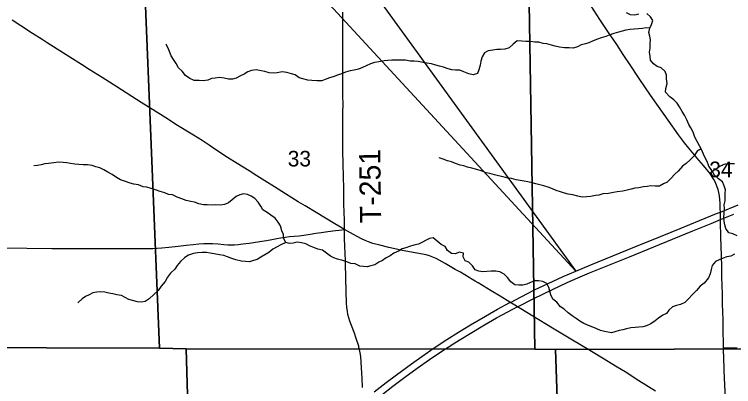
# Model space of a CAD drawing. Extents: x 0 to 34, y 0 to 22.
# Drawn here: x 13.115 to 15.039, y 13.199 to 14.196 of the extents above; entities that cross this region are included whole.
import ezdxf

# ---------------------------------------------------------------- set-up
doc = ezdxf.new("R2010")
doc.units = 0
for name, color, linetype in [('GM_X_County_Road', 7, 'Continuous'), ('GM_X_Interstate_Route', 7, 'Continuous'), ('GM_X_Minor_River', 7, 'Continuous'), ('GM_X_Section', 7, 'Continuous'), ('GM_X_Section_Text', 7, 'Continuous'), ('GM_X_State_Route', 7, 'Continuous'), ('GM_X_Township_Road', 7, 'Continuous'), ('GM_X_Township_Road_Text', 7, 'Continuous'), ('SH_Text', 7, 'Continuous')]:
    doc.layers.add(name, color=color, linetype=linetype)

msp = doc.modelspace()

# ---------------------------------------------------------------- linework, layer by layer
at = {"layer": 'GM_X_County_Road'}
for points in [[(14.9755, 13.7707), (14.9668, 13.7812), (14.9586, 13.7912), (14.9458, 13.8057), (14.9192, 13.8373), (14.9077, 13.8519), (14.8919, 13.8735), (14.8636, 13.9126), (14.8227, 13.9707), (14.8053, 13.9962), (14.7826, 14.03), (14.7641, 14.0579), (14.7439, 14.0885), (14.7265, 14.1152), (14.7027, 14.1505), (14.6816, 14.1823), (14.6568, 14.2195)], [(15.0124, 13.3029), (15.0119, 13.3151), (15.0111, 13.3488), (15.0107, 13.3777), (15.0096, 13.4211), (15.0092, 13.4459), (15.0085, 13.4706), (15.0079, 13.492), (15.0071, 13.5168), (15.0063, 13.5534), (15.0059, 13.5722), (15.0051, 13.6031), (15.0043, 13.637), (15.0041, 13.6463), (15.0036, 13.6567), (15.0036, 13.6668), (15.0033, 13.6758), (15.0027, 13.6908), (15.0022, 13.6999), (15.0012, 13.7102), (14.9998, 13.7188), (14.9979, 13.7268), (14.9946, 13.7362), (14.9908, 13.7455), (14.9865, 13.7537), (14.9819, 13.7612), (14.9789, 13.7658), (14.9755, 13.7707)], [(14.0369, 13.3041), (14.0367, 13.305), (14.0361, 13.3074), (14.0298, 13.3278), (14.0247, 13.3424), (14.0169, 13.3627), (14.0126, 13.3744), (14.0099, 13.3833), (14.0075, 13.3924), (14.0058, 13.4016), (14.0045, 13.4109), (14.0037, 13.4233), (14.0035, 13.4294), (14.003, 13.4475), (14.0025, 13.4631), (14.002, 13.4819), (14.0015, 13.5016), (14.001, 13.5178), (14.0005, 13.5359), (13.9996, 13.5557), (13.9989, 13.5752), (13.9983, 13.5957), (13.9978, 13.6199)], [(14.0465, 13.1967), (14.0456, 13.2216), (14.044, 13.2495), (14.0431, 13.2649), (14.0416, 13.2803), (14.0402, 13.2895), (14.0384, 13.2985), (14.0369, 13.3041)], [(15.0175, 13.1667), (15.0173, 13.1721), (15.0166, 13.1852), (15.016, 13.2036), (15.015, 13.2225), (15.0142, 13.2429), (15.0126, 13.2796), (15.0123, 13.2934), (15.0124, 13.3029)], [(15.0124, 13.3029), (15.0489, 13.3027)]]:
    msp.add_lwpolyline(points, dxfattribs=at)
at = {"layer": 'GM_X_Interstate_Route'}
for points in [[(14.0779, 13.1856), (14.1097, 13.2105), (14.1369, 13.2311), (14.1771, 13.2604), (14.2049, 13.2801), (14.2382, 13.303), (14.2411, 13.3049), (14.2719, 13.3252), (14.3033, 13.3452), (14.3351, 13.3645), (14.3753, 13.3881), (14.4077, 13.4064), (14.4405, 13.4241), (14.4418, 13.4247), (14.4708, 13.4399), (14.5068, 13.458), (14.5432, 13.4755), (14.5827, 13.4937), (14.6168, 13.5087), (14.6568, 13.5256), (14.7749, 13.5734), (14.8439, 13.6016), (14.8957, 13.6227), (14.9475, 13.6438), (14.9935, 13.6627), (15.0036, 13.6668), (15.051, 13.6862)], [(14.4597, 13.4127), (14.4608, 13.4132), (14.5043, 13.4348), (14.5546, 13.4593), (14.594, 13.4779), (14.6224, 13.4905), (14.6539, 13.5039), (14.7605, 13.5469), (14.8755, 13.594), (14.9302, 13.6164), (14.9792, 13.6362), (15.0041, 13.6463), (15.0396, 13.6607)], [(14.0978, 13.1775), (14.1273, 13.2004), (14.1596, 13.2247), (14.1923, 13.2483), (14.2255, 13.2715), (14.2616, 13.2958), (14.2757, 13.3049), (14.2929, 13.3161), (14.33, 13.339), (14.3726, 13.3646), (14.4049, 13.3832), (14.4349, 13.3998), (14.4597, 13.4127)]]:
    msp.add_lwpolyline(points, dxfattribs=at)
at = {"layer": 'GM_X_Minor_River'}
for points in [[(14.7852, 14.1967), (14.775, 14.1938), (14.7636, 14.1951), (14.7527, 14.2001)], [(15.0483, 13.6026), (15.0374, 13.6084), (15.0264, 13.6108), (15.0185, 13.6223), (15.0152, 13.6322), (15.0142, 13.6424), (15.0127, 13.6523), (15.0136, 13.6633), (15.0145, 13.6754), (15.0138, 13.6861), (15.0162, 13.697), (15.0163, 13.7168), (15.0172, 13.7266), (15.0138, 13.7369), (15.0094, 13.7479), (14.9985, 13.7556), (14.988, 13.7656), (14.9805, 13.7778), (14.973, 13.7893), (14.9682, 13.8019), (14.9634, 13.8118), (14.9589, 13.8221), (14.9533, 13.8339), (14.9477, 13.8438), (14.9414, 13.8556), (14.9354, 13.8674), (14.9306, 13.8808), (14.9247, 13.8918), (14.9194, 13.9014), (14.9135, 13.9132), (14.9075, 13.9258), (14.9016, 13.9357), (14.8945, 13.9483), (14.8877, 13.9578), (14.8787, 13.9674), (14.8682, 13.9755), (14.8569, 13.9873), (14.8578, 13.9976), (14.8613, 14.0108), (14.8599, 14.023), (14.8592, 14.0336), (14.8559, 14.0431), (14.8454, 14.0527), (14.8348, 14.0562), (14.8246, 14.0632), (14.8168, 14.0735), (14.8157, 14.0834), (14.8143, 14.0951), (14.8155, 14.1054), (14.8156, 14.1179), (14.8165, 14.1274), (14.815, 14.1376), (14.8121, 14.1475), (14.8152, 14.1593), (14.8195, 14.1691), (14.823, 14.1797), (14.8166, 14.1892), (14.8065, 14.198)], [(14.8152, 14.1593), (14.805, 14.1597), (14.7955, 14.1579), (14.7849, 14.1569), (14.7728, 14.1566), (14.7626, 14.1552), (14.7508, 14.1538), (14.7413, 14.1513), (14.7307, 14.1487), (14.7185, 14.145), (14.7064, 14.1402), (14.6969, 14.1369), (14.6847, 14.1328), (14.6749, 14.1295), (14.6635, 14.1247), (14.6521, 14.1202), (14.6426, 14.1173), (14.6316, 14.114), (14.6213, 14.1088), (14.6103, 14.1059), (14.5989, 14.1063), (14.5864, 14.1068), (14.5736, 14.1081), (14.5619, 14.1105), (14.5517, 14.1136), (14.5392, 14.1172), (14.5294, 14.1184), (14.518, 14.1212), (14.5074, 14.122), (14.4961, 14.1229), (14.4832, 14.1234), (14.4726, 14.1243), (14.4605, 14.1248), (14.4491, 14.1162), (14.4388, 14.1064), (14.4274, 14.1027), (14.4156, 14.1017), (14.4058, 14.1022), (14.3948, 14.1), (14.3826, 14.0982), (14.3724, 14.0926), (14.3666, 14.082), (14.3631, 14.0703), (14.3607, 14.0601), (14.3576, 14.0476), (14.3537, 14.0378), (14.342, 14.0337), (14.3306, 14.0369), (14.3174, 14.0423), (14.3069, 14.0462), (14.2947, 14.0463), (14.2849, 14.0476), (14.2751, 14.0503), (14.2634, 14.0546), (14.2524, 14.0577), (14.2422, 14.0601), (14.2305, 14.0633), (14.2188, 14.0657), (14.209, 14.0673), (14.195, 14.0697), (14.1847, 14.0709), (14.1738, 14.071), (14.1613, 14.073), (14.1382, 14.0733), (14.1249, 14.073), (14.114, 14.0724), (14.1041, 14.0713), (14.0901, 14.0692), (14.0783, 14.067), (14.0677, 14.0637), (14.0559, 14.0585), (14.0464, 14.0533), (14.0354, 14.0492), (14.024, 14.0467), (14.0134, 14.0445), (14.0008, 14.0408), (13.9898, 14.0371), (13.9792, 14.0335), (13.9678, 14.0286), (13.9579, 14.0261), (13.9469, 14.0212), (13.9374, 14.0183), (13.9238, 14.0177), (13.9109, 14.0193), (13.8999, 14.0202), (13.8871, 14.0233), (13.8765, 14.0265), (13.866, 14.0338), (13.8562, 14.0369), (13.8437, 14.0405), (13.8312, 14.0421), (13.8183, 14.0392), (13.8077, 14.0389), (13.7967, 14.0394), (13.785, 14.0429), (13.7752, 14.0445), (13.762, 14.0473), (13.7498, 14.0456), (13.7392, 14.0419), (13.7297, 14.0359), (13.7198, 14.031)], [(13.7198, 14.031), (13.7084, 14.0251), (13.6985, 14.0225), (13.6883, 14.0226), (13.6766, 14.0254), (13.6637, 14.027), (13.6523, 14.0253), (13.6428, 14.0242), (13.6322, 14.0201), (13.6201, 14.018), (13.6095, 14.0185), (13.5958, 14.019), (13.5842, 14.0244), (13.5729, 14.0321), (13.5642, 14.0439), (13.5545, 14.0528), (13.5481, 14.0642), (13.541, 14.0753), (13.5343, 14.0852), (13.5302, 14.0963), (13.5261, 14.1058), (13.5213, 14.1157), (13.5217, 14.1161)], [(14.9523, 13.8357), (14.9419, 13.8294), (14.9331, 13.817), (14.9224, 13.8069), (14.9121, 13.7971), (14.9026, 13.7892), (14.8911, 13.7764), (14.8816, 13.7682), (14.8713, 13.7565), (14.8609, 13.7464), (14.8514, 13.7419), (14.8404, 13.7359), (14.8294, 13.7364), (14.8177, 13.7365), (14.8082, 13.7355), (14.798, 13.7341), (14.7851, 13.7319), (14.7749, 13.7309), (14.7646, 13.7276), (14.754, 13.7254), (14.743, 13.7228), (14.7274, 13.7211), (14.7176, 13.7189), (14.7043, 13.716), (14.6891, 13.7154), (14.6789, 13.7121), (14.6694, 13.7107), (14.6565, 13.7081), (14.6467, 13.7071), (14.6342, 13.7068), (14.6224, 13.7088), (14.6088, 13.7124), (14.5967, 13.7148), (14.5865, 13.7172), (14.5764, 13.721), (14.5646, 13.7246), (14.5548, 13.7288), (14.5431, 13.7335), (14.5318, 13.737), (14.5208, 13.7398), (14.5103, 13.7426), (14.5001, 13.7449), (14.4887, 13.7477), (14.4789, 13.7493), (14.4573, 13.7533), (14.4453, 13.7565), (14.435, 13.7573), (14.423, 13.7612), (14.4097, 13.764), (14.3995, 13.7664), (14.3871, 13.7696), (14.3768, 13.7719), (14.364, 13.7766), (14.3523, 13.7805), (14.3387, 13.7841), (14.327, 13.7868), (14.3172, 13.7904), (14.3073, 13.7923), (14.2953, 13.7963), (14.2843, 13.8009), (14.2737, 13.8041), (14.2617, 13.8087), (14.2518, 13.8115), (14.2511, 13.8119)], [(14.1098, 13.5438), (14.0999, 13.5367), (14.0904, 13.5323), (14.079, 13.5255), (14.0684, 13.523), (14.0589, 13.52), (14.0487, 13.5205), (14.0388, 13.5221), (14.0264, 13.5276), (14.0151, 13.5292), (14.0041, 13.5331), (13.9939, 13.5374), (13.9799, 13.5409), (13.9701, 13.5441), (13.9603, 13.5487), (13.9498, 13.5564), (13.9392, 13.5649), (13.9271, 13.5676), (13.9162, 13.5715), (13.906, 13.575), (13.8951, 13.5812), (13.8834, 13.5844), (13.8716, 13.5864), (13.861, 13.5834), (13.8512, 13.5824), (13.841, 13.5848), (13.8354, 13.5966), (13.8351, 13.6068), (13.8306, 13.6168), (13.8273, 13.6297), (13.821, 13.64), (13.8123, 13.6499), (13.8007, 13.658), (13.7909, 13.6653), (13.78, 13.6723), (13.774, 13.6822), (13.7669, 13.6933), (13.7579, 13.7028), (13.7481, 13.7094), (13.7383, 13.714), (13.7281, 13.7157), (13.7182, 13.7131), (13.708, 13.7083), (13.6976, 13.6993), (13.6877, 13.6918), (13.6771, 13.6873), (13.6653, 13.6848), (13.6544, 13.6856), (13.6438, 13.6854), (13.6309, 13.6859), (13.621, 13.6863), (13.6089, 13.6887), (13.5972, 13.6934), (13.5867, 13.6946), (13.5746, 13.6978), (13.5629, 13.7025), (13.5508, 13.7068), (13.5383, 13.713), (13.5277, 13.7138), (13.5179, 13.7185), (13.5055, 13.722), (13.4923, 13.7263), (13.4813, 13.7294), (13.4696, 13.7334), (13.4598, 13.7342), (13.4473, 13.7393), (13.4344, 13.7417), (13.4246, 13.744), (13.4122, 13.7487), (13.3986, 13.7526), (13.3884, 13.7596), (13.3767, 13.7673), (13.365, 13.7735), (13.3545, 13.7796), (13.3439, 13.7847), (13.333, 13.7882), (13.3228, 13.7909), (13.3107, 13.793), (13.2989, 13.7927), (13.2876, 13.7939), (13.277, 13.7952), (13.2653, 13.7968), (13.2554, 13.7988), (13.2456, 13.7997), (13.2323, 13.8002), (13.221, 13.7988), (13.2066, 13.7963), (13.1963, 13.7956), (13.1869, 13.7934), (13.177, 13.7912), (13.1668, 13.7902), (13.1671, 13.7902)], [(13.841, 13.5848), (13.828, 13.5785), (13.8178, 13.5732), (13.8067, 13.5669), (13.796, 13.5583), (13.785, 13.5519), (13.7744, 13.5456), (13.7648, 13.54), (13.755, 13.5367), (13.7443, 13.533), (13.733, 13.5342), (13.7224, 13.5351), (13.7077, 13.539), (13.6967, 13.5426), (13.6854, 13.5465), (13.6756, 13.55), (13.6638, 13.552), (13.6498, 13.5548), (13.6389, 13.5564), (13.629, 13.5584), (13.6177, 13.5585), (13.6052, 13.5575), (13.5942, 13.5557), (13.5813, 13.5516), (13.5714, 13.5453), (13.5595, 13.534), (13.5507, 13.5239), (13.5442, 13.5141), (13.5332, 13.5028), (13.5251, 13.4919), (13.5182, 13.4805), (13.5082, 13.4681), (13.5002, 13.4568), (13.4758, 13.4343), (13.4651, 13.4276), (13.4556, 13.4254), (13.4446, 13.4266), (13.4344, 13.4294), (13.4216, 13.4329), (13.4118, 13.4376), (13.4016, 13.4434), (13.3895, 13.4446), (13.3789, 13.4481), (13.3676, 13.4498), (13.357, 13.4518), (13.3464, 13.453), (13.3354, 13.4524), (13.3252, 13.4506), (13.3153, 13.4453), (13.3058, 13.4405), (13.2963, 13.4341), (13.286, 13.4248), (13.2848, 13.424)], [(15.0414, 13.5541), (15.0312, 13.5489), (15.0213, 13.5471), (15.0107, 13.543), (15.0008, 13.5386), (14.9909, 13.5345), (14.9817, 13.5236), (14.979, 13.513), (14.9766, 13.5009), (14.9716, 13.4903), (14.9605, 13.4767), (14.9495, 13.4685), (14.9399, 13.4568), (14.9284, 13.4448), (14.9185, 13.4339), (14.9082, 13.4245), (14.8972, 13.4189), (14.8862, 13.4164), (14.8755, 13.4127), (14.866, 13.4044), (14.8595, 13.3946), (14.8496, 13.3902), (14.8385, 13.3827), (14.829, 13.3756), (14.818, 13.3673), (14.8062, 13.3621), (14.7963, 13.3596), (14.7853, 13.3585), (14.7755, 13.3575), (14.7641, 13.3568), (14.7523, 13.3543), (14.7429, 13.3517), (14.733, 13.3492), (14.7216, 13.3459), (14.7121, 13.3437), (14.6936, 13.3465), (14.6826, 13.3493), (14.6728, 13.3536), (14.6623, 13.3582), (14.6509, 13.3625), (14.6385, 13.3683), (14.6279, 13.3741), (14.6182, 13.3814), (14.6072, 13.3891), (14.5967, 13.3964), (14.5862, 13.4068), (14.5764, 13.4133), (14.5659, 13.4256), (14.5554, 13.4333), (14.5505, 13.4454), (14.5476, 13.455), (14.5446, 13.4648), (14.5394, 13.4751), (14.5285, 13.4809), (14.5168, 13.4822), (14.5062, 13.4823), (14.4955, 13.4778), (14.4856, 13.4734), (14.4754, 13.4708), (14.4644, 13.4713), (14.4542, 13.4718), (14.4433, 13.4795), (14.4339, 13.491), (14.4249, 13.5005), (14.414, 13.5063), (14.4034, 13.5083), (14.3905, 13.5088), (14.3788, 13.5078), (14.3678, 13.5068), (14.3579, 13.508), (14.3481, 13.5123), (14.3403, 13.5226), (14.3309, 13.5322), (14.3207, 13.5365), (14.3159, 13.5468), (14.3163, 13.5562), (14.3046, 13.559), (14.2947, 13.5546), (14.2841, 13.5554), (14.2736, 13.5635), (14.2673, 13.5742), (14.2567, 13.58), (14.2465, 13.5888), (14.2353, 13.598), (14.2258, 13.5962), (14.1965, 13.5806), (14.184, 13.5776), (14.1722, 13.5747), (14.1623, 13.571), (14.1525, 13.5681), (14.1426, 13.5621), (14.13, 13.5569), (14.1205, 13.5494), (14.1098, 13.5438)]]:
    msp.add_lwpolyline(points, dxfattribs=at)
at = {"layer": 'GM_X_Section'}
for points in [[(13.4623, 14.3061), (13.5034, 13.3022), (12.5967, 13.3052), (12.4929, 13.3075), (12.486, 14.3129), (12.9117, 14.2993)], [(14.4911, 14.2816), (14.5077, 13.2997), (13.5746, 13.3006), (13.5034, 13.3022), (13.4623, 14.3061), (13.6079, 14.3123), (13.9911, 14.2848)], [(15.5087, 14.2889), (15.5148, 13.3016), (14.5623, 13.2983), (14.5077, 13.2997), (14.4911, 14.2816)], [(13.5034, 13.3022), (13.5746, 13.3006), (13.6043, 12.2869), (12.6535, 12.2476), (12.5967, 13.3052)], [(14.5623, 13.2983), (14.5977, 12.2808), (13.6043, 12.2869), (13.5746, 13.3006), (14.5077, 13.2997)], [(15.5625, 13.3022), (15.5907, 12.2877), (15.0525, 12.2941), (14.5977, 12.2808), (14.5623, 13.2983), (15.5148, 13.3016)]]:
    msp.add_lwpolyline(points, close=True, dxfattribs=at)
at = {"layer": 'GM_X_State_Route'}
for points in [[(14.641, 13.3044), (14.5949, 13.332), (14.5549, 13.356), (14.5019, 13.3883), (14.47, 13.4076), (14.4608, 13.4132), (14.4418, 13.4247), (14.4408, 13.4253), (14.4144, 13.4416), (14.3904, 13.456), (14.3559, 13.477), (14.3478, 13.4816), (14.3371, 13.4878), (14.332, 13.4913), (14.3081, 13.5057), (14.2945, 13.5132), (14.2809, 13.5207), (14.2675, 13.5285), (14.2514, 13.5379), (14.2431, 13.5423), (14.2346, 13.5462), (14.2258, 13.5494), (14.2168, 13.5521), (14.1527, 13.5641), (14.1376, 13.5672), (14.1165, 13.5722), (14.0924, 13.5781), (14.0744, 13.5828), (14.0624, 13.5868), (14.0535, 13.5904), (14.0436, 13.5949), (14.0321, 13.6009), (14.0222, 13.6063), (13.9978, 13.6199), (13.9724, 13.6351), (13.9224, 13.6655), (13.893, 13.683), (13.8745, 13.6943), (13.8402, 13.7156), (13.8113, 13.7338), (13.7851, 13.7505), (13.7641, 13.7639), (13.7431, 13.7771), (13.7112, 13.7963), (13.685, 13.813), (13.6537, 13.8332), (13.6359, 13.8456), (13.6179, 13.8579), (13.5941, 13.8727), (13.5517, 13.8986), (13.5203, 13.9187), (13.4916, 13.9372), (13.4547, 13.9604), (13.389, 14.0017), (13.3497, 14.0268), (13.3155, 14.0484), (13.2946, 14.0617), (13.2631, 14.0816), (13.2028, 14.12), (13.1899, 14.1286), (13.1636, 14.1452), (13.1323, 14.1654), (13.1088, 14.1805)], [(14.8304, 13.1873), (14.7856, 13.2152), (14.7489, 13.2385), (14.7278, 13.2516), (14.6879, 13.2757), (14.6429, 13.3033), (14.641, 13.3044)]]:
    msp.add_lwpolyline(points, dxfattribs=at)
at = {"layer": 'GM_X_Township_Road'}
for points in [[(13.9978, 13.6199), (13.9978, 13.6378), (13.9978, 13.6491), (13.9973, 13.6621), (13.9973, 13.6708), (13.9968, 13.6837), (13.9968, 13.6946), (13.9968, 13.7073), (13.9967, 13.7215), (13.9962, 13.7318), (13.9962, 13.7413), (13.9957, 13.7507), (13.9957, 13.7591), (13.9945, 13.7986), (13.9938, 13.8276), (13.9938, 13.8448), (13.994, 13.8705), (13.9938, 13.9043), (13.9941, 13.9292), (13.9942, 13.9599), (13.9941, 13.9723), (13.9938, 13.9878), (13.9937, 14.0001), (13.9939, 14.0155), (13.994, 14.0279), (13.9941, 14.0404), (13.994, 14.0527), (13.9939, 14.0719), (13.9937, 14.0876), (13.9939, 14.1), (13.9939, 14.1161), (13.9936, 14.1374), (13.9938, 14.1617), (13.9938, 14.2022)], [(14.9755, 13.7707), (14.9799, 13.774), (14.9858, 13.7785), (15.0026, 13.7897), (15.0085, 13.7926), (15.0115, 13.7939), (15.0142, 13.7946), (15.0172, 13.7954), (15.0198, 13.7958), (15.0228, 13.7963), (15.0293, 13.7967), (15.0416, 13.7968)], [(13.092, 13.5705), (13.1489, 13.5696), (13.215, 13.5691), (13.2599, 13.5689), (13.3042, 13.5689), (13.3511, 13.5689), (13.4345, 13.5687), (13.4645, 13.5687), (13.4852, 13.5691), (13.51, 13.5707), (13.5285, 13.5725), (13.5532, 13.5751), (13.5744, 13.5777), (13.5932, 13.5798), (13.6087, 13.5814), (13.6215, 13.5823), (13.6334, 13.5826), (13.6455, 13.5823), (13.6602, 13.5814), (13.6758, 13.5801), (13.6862, 13.579), (13.6945, 13.5786), (13.7042, 13.579), (13.7138, 13.5798), (13.7259, 13.5812), (13.7345, 13.5824), (13.743, 13.5836), (13.7498, 13.5845), (13.7771, 13.5887), (13.7893, 13.5908), (13.804, 13.5933), (13.817, 13.5957), (13.8267, 13.5974), (13.8399, 13.5995), (13.8511, 13.6009), (13.8639, 13.6022), (13.877, 13.6033), (13.8891, 13.6049), (13.9067, 13.6075), (13.9214, 13.6097), (13.9358, 13.6117), (13.9534, 13.6142), (13.9742, 13.6171), (13.9835, 13.6184), (13.9978, 13.6199)]]:
    msp.add_lwpolyline(points, dxfattribs=at)
at = {"layer": 'SH_Text'}
msp.add_lwpolyline([(13.4612, 15.1029), (14.6168, 13.5087), (13.4612, 14.7614)], close=True, dxfattribs=at)

# ---------------------------------------------------------------- texts
at = {"layer": 'GM_X_Section_Text'}
for s, p in [('33', (13.8463, 13.7887)), ('34', (14.9738, 13.7599))]:
    msp.add_text(s, height=0.04186, rotation=0, dxfattribs=at).set_placement(p)
at = {"layer": 'GM_X_Township_Road_Text'}
msp.add_text('T-251', height=0.05682, rotation=90.8309, dxfattribs=at).set_placement((14.0966, 13.6376))

doc.saveas('drawing.dxf')
